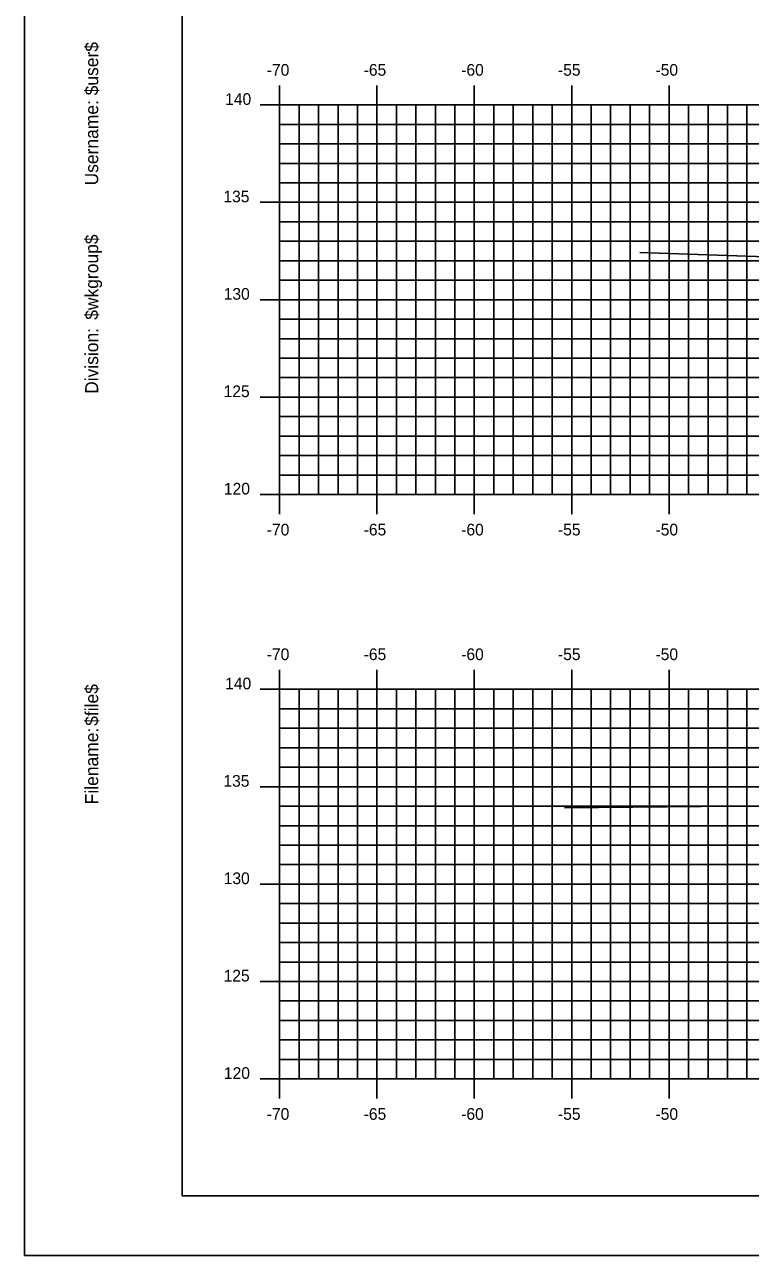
# Model space of a CAD drawing. Extents: x 1145638 to 1145808, y 608981 to 609091.
# Drawn here: x 1145637.6 to 1145674.8, y 608981.3 to 609044.5 of the extents above; entities that cross this region are included whole.
import ezdxf

# ---------------------------------------------------------------- set-up
doc = ezdxf.new("R2010")
doc.units = 0
for name, color, linetype in [('BORDER', 7, 'Continuous'), ('H_V ANNOTATION', 7, 'Continuous'), ('MAJOR', 7, 'Continuous'), ('MINOR', 7, 'Continuous'), ('PLOT BOUNDARY', 7, 'Continuous'), ('S_Roadway_Centerline', 7, 'Continuous')]:
    doc.layers.add(name, color=color, linetype=linetype)

msp = doc.modelspace()

# ---------------------------------------------------------------- linework, layer by layer
at = {"layer": 'BORDER'}
msp.add_lwpolyline([(1145645.645, 608984.335), (1145805.645, 608984.335), (1145805.645, 609089.335), (1145645.645, 609089.335)], close=True, dxfattribs=at)
at = {"layer": 'MAJOR'}
for p, q in [((1145650.645, 609041.337), (1145650.645, 609040.335)), ((1145655.645, 609041.337), (1145655.645, 609040.335)), ((1145660.645, 609041.337), (1145660.645, 609040.335)), ((1145665.645, 609041.337), (1145665.645, 609040.335)), ((1145670.645, 609041.337), (1145670.645, 609040.335)), ((1145649.643, 609040.335), (1145650.645, 609040.335)), ((1145650.645, 609040.335), (1145790.645, 609040.335)), ((1145650.645, 609020.335), (1145650.645, 609040.335)), ((1145650.645, 609020.335), (1145650.645, 609040.335)), ((1145650.645, 609040.335), (1145790.645, 609040.335)), ((1145655.645, 609020.335), (1145655.645, 609040.335)), ((1145660.645, 609020.335), (1145660.645, 609040.335)), ((1145665.645, 609020.335), (1145665.645, 609040.335)), ((1145670.645, 609020.335), (1145670.645, 609040.335)), ((1145649.643, 609035.335), (1145650.645, 609035.335)), ((1145650.645, 609035.335), (1145790.645, 609035.335)), ((1145649.643, 609030.335), (1145650.645, 609030.335)), ((1145650.645, 609030.335), (1145790.645, 609030.335)), ((1145649.643, 609025.335), (1145650.645, 609025.335)), ((1145650.645, 609025.335), (1145790.645, 609025.335)), ((1145649.643, 609020.335), (1145650.645, 609020.335)), ((1145650.645, 609020.335), (1145790.645, 609020.335)), ((1145650.645, 609020.335), (1145790.645, 609020.335)), ((1145650.645, 609019.333), (1145650.645, 609020.335)), ((1145655.645, 609019.333), (1145655.645, 609020.335)), ((1145660.645, 609019.333), (1145660.645, 609020.335)), ((1145665.645, 609019.333), (1145665.645, 609020.335)), ((1145670.645, 609019.333), (1145670.645, 609020.335)), ((1145650.645, 609011.337), (1145650.645, 609010.335)), ((1145655.645, 609011.337), (1145655.645, 609010.335)), ((1145660.645, 609011.337), (1145660.645, 609010.335)), ((1145665.645, 609011.337), (1145665.645, 609010.335)), ((1145670.645, 609011.337), (1145670.645, 609010.335)), ((1145649.643, 609010.335), (1145650.645, 609010.335)), ((1145650.645, 609010.335), (1145790.645, 609010.335)), ((1145650.645, 608990.335), (1145650.645, 609010.335)), ((1145650.645, 608990.335), (1145650.645, 609010.335)), ((1145650.645, 609010.335), (1145790.645, 609010.335)), ((1145655.645, 608990.335), (1145655.645, 609010.335)), ((1145660.645, 608990.335), (1145660.645, 609010.335)), ((1145665.645, 608990.335), (1145665.645, 609010.335)), ((1145670.645, 608990.335), (1145670.645, 609010.335)), ((1145649.643, 609005.335), (1145650.645, 609005.335)), ((1145650.645, 609005.335), (1145790.645, 609005.335)), ((1145649.643, 609000.335), (1145650.645, 609000.335)), ((1145650.645, 609000.335), (1145790.645, 609000.335)), ((1145649.643, 608995.335), (1145650.645, 608995.335)), ((1145650.645, 608995.335), (1145790.645, 608995.335)), ((1145649.643, 608990.335), (1145650.645, 608990.335)), ((1145650.645, 608990.335), (1145790.645, 608990.335)), ((1145650.645, 608990.335), (1145790.645, 608990.335)), ((1145650.645, 608989.333), (1145650.645, 608990.335)), ((1145655.645, 608989.333), (1145655.645, 608990.335)), ((1145660.645, 608989.333), (1145660.645, 608990.335)), ((1145665.645, 608989.333), (1145665.645, 608990.335)), ((1145670.645, 608989.333), (1145670.645, 608990.335))]:
    msp.add_line(p, q, dxfattribs=at)
at = {"layer": 'MINOR'}
for p, q in [((1145651.645, 609020.335), (1145651.645, 609040.335)), ((1145652.645, 609020.335), (1145652.645, 609040.335)), ((1145653.645, 609020.335), (1145653.645, 609040.335)), ((1145654.645, 609020.335), (1145654.645, 609040.335)), ((1145656.645, 609020.335), (1145656.645, 609040.335)), ((1145657.645, 609020.335), (1145657.645, 609040.335)), ((1145658.645, 609020.335), (1145658.645, 609040.335)), ((1145659.645, 609020.335), (1145659.645, 609040.335)), ((1145661.645, 609020.335), (1145661.645, 609040.335)), ((1145662.645, 609020.335), (1145662.645, 609040.335)), ((1145663.645, 609020.335), (1145663.645, 609040.335)), ((1145664.645, 609020.335), (1145664.645, 609040.335)), ((1145666.645, 609020.335), (1145666.645, 609040.335)), ((1145667.645, 609020.335), (1145667.645, 609040.335)), ((1145668.645, 609020.335), (1145668.645, 609040.335)), ((1145669.645, 609020.335), (1145669.645, 609040.335)), ((1145671.645, 609020.335), (1145671.645, 609040.335)), ((1145672.645, 609020.335), (1145672.645, 609040.335)), ((1145673.645, 609020.335), (1145673.645, 609040.335)), ((1145674.645, 609020.335), (1145674.645, 609040.335)), ((1145650.645, 609039.335), (1145790.645, 609039.335)), ((1145650.645, 609039.335), (1145651.647, 609039.335)), ((1145650.645, 609038.335), (1145790.645, 609038.335)), ((1145650.645, 609038.335), (1145651.647, 609038.335)), ((1145650.645, 609037.335), (1145790.645, 609037.335)), ((1145650.645, 609037.335), (1145651.647, 609037.335)), ((1145650.645, 609036.335), (1145790.645, 609036.335)), ((1145650.645, 609036.335), (1145651.647, 609036.335)), ((1145650.645, 609034.335), (1145790.645, 609034.335)), ((1145650.645, 609034.335), (1145651.647, 609034.335)), ((1145650.645, 609033.335), (1145790.645, 609033.335)), ((1145650.645, 609033.335), (1145651.647, 609033.335)), ((1145650.645, 609032.335), (1145790.645, 609032.335)), ((1145650.645, 609032.335), (1145651.647, 609032.335)), ((1145650.645, 609031.335), (1145790.645, 609031.335)), ((1145650.645, 609031.335), (1145651.647, 609031.335)), ((1145650.645, 609029.335), (1145790.645, 609029.335)), ((1145650.645, 609029.335), (1145651.647, 609029.335)), ((1145650.645, 609028.335), (1145790.645, 609028.335)), ((1145650.645, 609028.335), (1145651.647, 609028.335)), ((1145650.645, 609027.335), (1145790.645, 609027.335)), ((1145650.645, 609027.335), (1145651.647, 609027.335)), ((1145650.645, 609026.335), (1145790.645, 609026.335)), ((1145650.645, 609026.335), (1145651.647, 609026.335)), ((1145650.645, 609024.335), (1145790.645, 609024.335)), ((1145650.645, 609024.335), (1145651.647, 609024.335)), ((1145650.645, 609023.335), (1145790.645, 609023.335)), ((1145650.645, 609023.335), (1145651.647, 609023.335)), ((1145650.645, 609022.335), (1145790.645, 609022.335)), ((1145650.645, 609022.335), (1145651.647, 609022.335)), ((1145650.645, 609021.335), (1145790.645, 609021.335)), ((1145650.645, 609021.335), (1145651.647, 609021.335)), ((1145651.645, 608990.335), (1145651.645, 609010.335)), ((1145652.645, 608990.335), (1145652.645, 609010.335)), ((1145653.645, 608990.335), (1145653.645, 609010.335)), ((1145654.645, 608990.335), (1145654.645, 609010.335)), ((1145656.645, 608990.335), (1145656.645, 609010.335)), ((1145657.645, 608990.335), (1145657.645, 609010.335)), ((1145658.645, 608990.335), (1145658.645, 609010.335)), ((1145659.645, 608990.335), (1145659.645, 609010.335)), ((1145661.645, 608990.335), (1145661.645, 609010.335)), ((1145662.645, 608990.335), (1145662.645, 609010.335)), ((1145663.645, 608990.335), (1145663.645, 609010.335)), ((1145664.645, 608990.335), (1145664.645, 609010.335)), ((1145666.645, 608990.335), (1145666.645, 609010.335)), ((1145667.645, 608990.335), (1145667.645, 609010.335)), ((1145668.645, 608990.335), (1145668.645, 609010.335)), ((1145669.645, 608990.335), (1145669.645, 609010.335)), ((1145671.645, 608990.335), (1145671.645, 609010.335)), ((1145672.645, 608990.335), (1145672.645, 609010.335)), ((1145673.645, 608990.335), (1145673.645, 609010.335)), ((1145674.645, 608990.335), (1145674.645, 609010.335)), ((1145650.645, 609009.335), (1145790.645, 609009.335)), ((1145650.645, 609009.335), (1145651.647, 609009.335)), ((1145650.645, 609008.335), (1145790.645, 609008.335)), ((1145650.645, 609008.335), (1145651.647, 609008.335)), ((1145650.645, 609007.335), (1145790.645, 609007.335)), ((1145650.645, 609007.335), (1145651.647, 609007.335)), ((1145650.645, 609006.335), (1145790.645, 609006.335)), ((1145650.645, 609006.335), (1145651.647, 609006.335)), ((1145650.645, 609004.335), (1145790.645, 609004.335)), ((1145650.645, 609004.335), (1145651.647, 609004.335)), ((1145650.645, 609003.335), (1145790.645, 609003.335)), ((1145650.645, 609003.335), (1145651.647, 609003.335)), ((1145650.645, 609002.335), (1145790.645, 609002.335)), ((1145650.645, 609002.335), (1145651.647, 609002.335)), ((1145650.645, 609001.335), (1145790.645, 609001.335)), ((1145650.645, 609001.335), (1145651.647, 609001.335)), ((1145650.645, 608999.335), (1145790.645, 608999.335)), ((1145650.645, 608999.335), (1145651.647, 608999.335)), ((1145650.645, 608998.335), (1145790.645, 608998.335)), ((1145650.645, 608998.335), (1145651.647, 608998.335)), ((1145650.645, 608997.335), (1145790.645, 608997.335)), ((1145650.645, 608997.335), (1145651.647, 608997.335)), ((1145650.645, 608996.335), (1145790.645, 608996.335)), ((1145650.645, 608996.335), (1145651.647, 608996.335)), ((1145650.645, 608994.335), (1145790.645, 608994.335)), ((1145650.645, 608994.335), (1145651.647, 608994.335)), ((1145650.645, 608993.335), (1145790.645, 608993.335)), ((1145650.645, 608993.335), (1145651.647, 608993.335)), ((1145650.645, 608992.335), (1145790.645, 608992.335)), ((1145650.645, 608992.335), (1145651.647, 608992.335)), ((1145650.645, 608991.335), (1145790.645, 608991.335)), ((1145650.645, 608991.335), (1145651.647, 608991.335))]:
    msp.add_line(p, q, dxfattribs=at)
at = {"layer": 'PLOT BOUNDARY'}
msp.add_lwpolyline([(1145637.552, 608981.276), (1145807.552, 608981.276), (1145807.552, 609091.276), (1145637.552, 609091.276)], close=True, dxfattribs=at)
at = {"layer": 'S_Roadway_Centerline'}
for points in [[(1145669.136, 609032.753), (1145680.62, 609032.361), (1145689.164, 609032.105), (1145700.503, 609028.355), (1145700.592, 609028.328), (1145700.97, 609028.382), (1145704.281, 609028.863), (1145704.322, 609028.867), (1145707.646, 609029.095), (1145707.961, 609029.103), (1145718.638, 609029.518), (1145719.177, 609029.498), (1145729.939, 609029.23), (1145730.211, 609029.201), (1145733.672, 609028.828), (1145734.305, 609028.732), (1145741.113, 609027.276), (1145743.374, 609027.926), (1145746.672, 609028.664), (1145751.599, 609029.075), (1145765.021, 609029.966)], [(1145665.284, 609004.253), (1145674.048, 609004.329), (1145676.611, 609004.338), (1145686.027, 609003.803), (1145691.493, 609003.283), (1145697.515, 609000.943), (1145701.06, 608999.985), (1145703.047, 609000.3), (1145704.751, 609000.59), (1145706.442, 609000.759), (1145707.087, 609000.832), (1145707.467, 609000.81), (1145715.52, 609001.007), (1145718.557, 609001.09), (1145727.194, 609000.779), (1145729.795, 609000.725), (1145730.727, 609000.642), (1145734.227, 609000.27), (1145736.145, 608999.62), (1145736.754, 608999.333), (1145745.298, 609002.239), (1145746.848, 609002.934), (1145749.998, 609003.03), (1145766.074, 609004.643)]]:
    msp.add_lwpolyline(points, dxfattribs=at)

# ---------------------------------------------------------------- texts
at = {"layer": 'BORDER'}
for s, p in [('$user$', (1145641.33, 609040.827)), ('Username:', (1145641.33, 609036.203)), ('$wkgroup$', (1145641.33, 609029.305)), ('Division:', (1145641.33, 609025.501)), ('$file$', (1145641.33, 609008.461)), ('Filename:', (1145641.33, 609004.433))]:
    msp.add_text(s, height=0.6696, rotation=90, dxfattribs=at).set_placement(p)
at = {"layer": 'H_V ANNOTATION'}
for s, p in [('-70', (1145649.987, 609041.835)), ('-65', (1145654.963, 609041.835)), ('-60', (1145659.971, 609041.835)), ('-55', (1145664.941, 609041.835)), ('-50', (1145669.949, 609041.835)), ('140', (1145647.85, 609040.335)), ('135', (1145647.759, 609035.335)), ('130', (1145647.775, 609030.335)), ('125', (1145647.77, 609025.335)), ('120', (1145647.786, 609020.335)), ('-70', (1145649.987, 609018.235)), ('-65', (1145654.963, 609018.235)), ('-60', (1145659.971, 609018.235)), ('-55', (1145664.941, 609018.235)), ('-50', (1145669.949, 609018.235)), ('-70', (1145649.987, 609011.835)), ('-65', (1145654.963, 609011.835)), ('-60', (1145659.971, 609011.835)), ('-55', (1145664.941, 609011.835)), ('-50', (1145669.949, 609011.835)), ('140', (1145647.85, 609010.335)), ('135', (1145647.759, 609005.335)), ('130', (1145647.775, 609000.335)), ('125', (1145647.77, 608995.335)), ('120', (1145647.786, 608990.335)), ('-70', (1145649.987, 608988.235)), ('-65', (1145654.963, 608988.235)), ('-60', (1145659.971, 608988.235)), ('-55', (1145664.941, 608988.235)), ('-50', (1145669.949, 608988.235))]:
    msp.add_text(s, height=0.6, dxfattribs=at).set_placement(p)
at = {"layer": 'MAJOR'}
for p in [(1145650.641, 609020.335), (1145650.641, 608990.335)]:
    msp.add_text('-', height=0.006, dxfattribs=at).set_placement(p)

doc.saveas('drawing.dxf')
